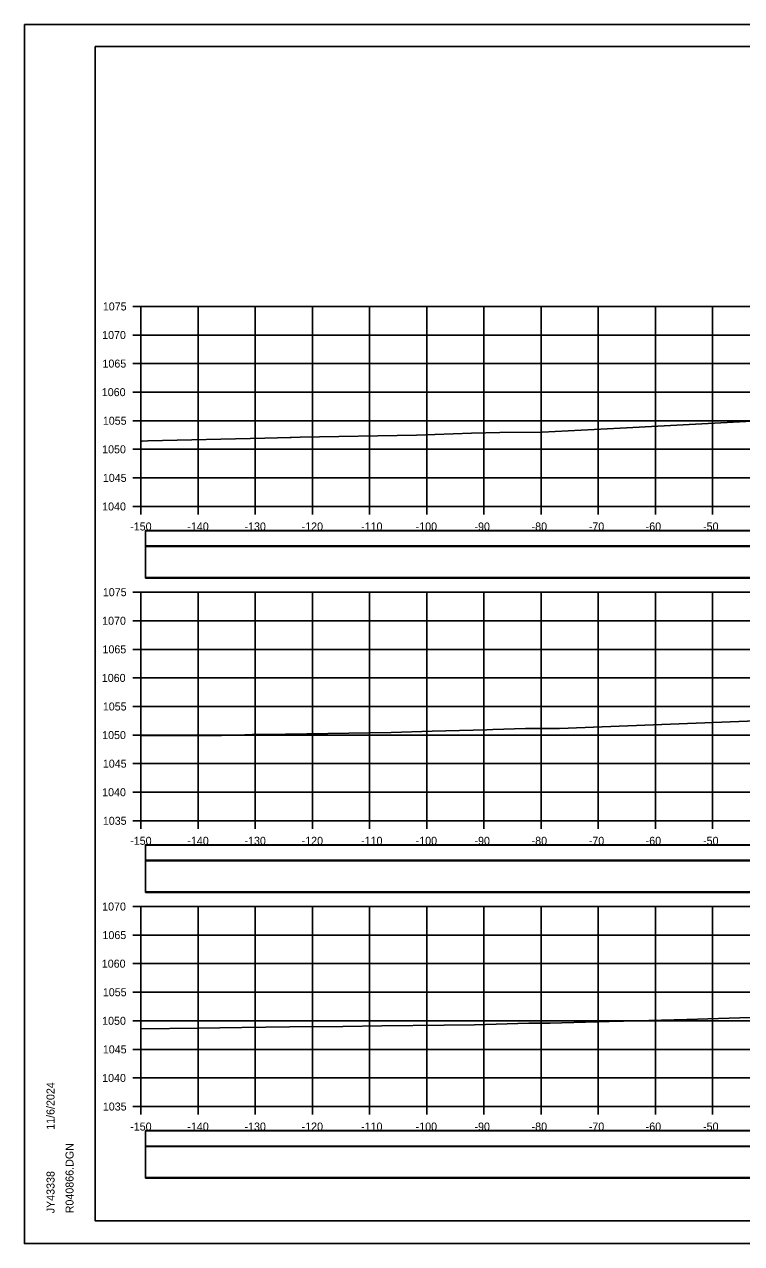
# Model space of a CAD drawing. Extents: x 1370565 to 1374448, y 301010 to 304637.
# Drawn here: x 1373198.4 to 1373323.9, y 303431.7 to 303645 of the extents above; entities that cross this region are included whole.
import ezdxf

# ---------------------------------------------------------------- set-up
doc = ezdxf.new("R2010")
doc.units = 0
for name, color, linetype in [('Default', 7, 'Continuous'), ('R_Axis', 7, 'Continuous'), ('R_Axis Annot', 7, 'Continuous'), ('R_Border', 7, 'Continuous'), ('R_Drive', 7, 'Continuous'), ('R_Exist Surface', 7, 'Continuous'), ('R_Grid', 7, 'Continuous'), ('R_No Plot', 7, 'Continuous')]:
    doc.layers.add(name, color=color, linetype=linetype)

msp = doc.modelspace()

# ---------------------------------------------------------------- linework, layer by layer
at = {"layer": 'Default'}
for points in [[(1373219.61, 303553.72), (1373518.02, 303553.72), (1373518.02, 303556.42), (1373219.61, 303556.42)], [(1373219.61, 303548.14), (1373518.02, 303548.14), (1373518.02, 303553.66), (1373219.61, 303553.66)], [(1373219.61, 303498.72), (1373518.02, 303498.72), (1373518.02, 303501.42), (1373219.61, 303501.42)], [(1373219.61, 303493.14), (1373518.02, 303493.14), (1373518.02, 303498.66), (1373219.61, 303498.66)], [(1373219.61, 303448.72), (1373518.02, 303448.72), (1373518.02, 303451.42), (1373219.61, 303451.42)], [(1373219.61, 303443.14), (1373518.02, 303443.14), (1373518.02, 303448.66), (1373219.61, 303448.66)]]:
    msp.add_lwpolyline(points, close=True, dxfattribs=at)
at = {"layer": 'R_Axis'}
for p, q in [((1373217.41, 303595.68), (1373218.81, 303595.68)), ((1373218.81, 303560.68), (1373218.81, 303595.68)), ((1373217.41, 303590.68), (1373218.81, 303590.68)), ((1373217.41, 303585.68), (1373218.81, 303585.68)), ((1373217.41, 303580.68), (1373218.81, 303580.68)), ((1373217.41, 303575.68), (1373218.81, 303575.68)), ((1373217.41, 303570.68), (1373218.81, 303570.68)), ((1373217.41, 303565.68), (1373218.81, 303565.68)), ((1373217.41, 303560.68), (1373218.81, 303560.68)), ((1373218.81, 303560.68), (1373518.81, 303560.68)), ((1373218.81, 303559.28), (1373218.81, 303560.68)), ((1373228.81, 303559.28), (1373228.81, 303560.68)), ((1373238.81, 303559.28), (1373238.81, 303560.68)), ((1373248.81, 303559.28), (1373248.81, 303560.68)), ((1373258.81, 303559.28), (1373258.81, 303560.68)), ((1373268.81, 303559.28), (1373268.81, 303560.68)), ((1373278.81, 303559.28), (1373278.81, 303560.68)), ((1373288.81, 303559.28), (1373288.81, 303560.68)), ((1373298.81, 303559.28), (1373298.81, 303560.68)), ((1373308.81, 303559.28), (1373308.81, 303560.68)), ((1373318.81, 303559.28), (1373318.81, 303560.68)), ((1373217.41, 303545.68), (1373218.81, 303545.68)), ((1373218.81, 303505.68), (1373218.81, 303545.68)), ((1373217.41, 303540.68), (1373218.81, 303540.68)), ((1373217.41, 303535.68), (1373218.81, 303535.68)), ((1373217.41, 303530.68), (1373218.81, 303530.68)), ((1373217.41, 303525.68), (1373218.81, 303525.68)), ((1373217.41, 303520.68), (1373218.81, 303520.68)), ((1373217.41, 303515.68), (1373218.81, 303515.68)), ((1373217.41, 303510.68), (1373218.81, 303510.68)), ((1373217.41, 303505.68), (1373218.81, 303505.68)), ((1373218.81, 303505.68), (1373518.81, 303505.68)), ((1373218.81, 303504.28), (1373218.81, 303505.68)), ((1373228.81, 303504.28), (1373228.81, 303505.68)), ((1373238.81, 303504.28), (1373238.81, 303505.68)), ((1373248.81, 303504.28), (1373248.81, 303505.68)), ((1373258.81, 303504.28), (1373258.81, 303505.68)), ((1373268.81, 303504.28), (1373268.81, 303505.68)), ((1373278.81, 303504.28), (1373278.81, 303505.68)), ((1373288.81, 303504.28), (1373288.81, 303505.68)), ((1373298.81, 303504.28), (1373298.81, 303505.68)), ((1373308.81, 303504.28), (1373308.81, 303505.68)), ((1373318.81, 303504.28), (1373318.81, 303505.68)), ((1373217.41, 303490.68), (1373218.81, 303490.68)), ((1373218.81, 303455.68), (1373218.81, 303490.68)), ((1373217.41, 303485.68), (1373218.81, 303485.68)), ((1373217.41, 303480.68), (1373218.81, 303480.68)), ((1373217.41, 303475.68), (1373218.81, 303475.68)), ((1373217.41, 303470.68), (1373218.81, 303470.68)), ((1373217.41, 303465.68), (1373218.81, 303465.68)), ((1373217.41, 303460.68), (1373218.81, 303460.68)), ((1373217.41, 303455.68), (1373218.81, 303455.68)), ((1373218.81, 303455.68), (1373518.81, 303455.68)), ((1373218.81, 303454.28), (1373218.81, 303455.68)), ((1373228.81, 303454.28), (1373228.81, 303455.68)), ((1373238.81, 303454.28), (1373238.81, 303455.68)), ((1373248.81, 303454.28), (1373248.81, 303455.68)), ((1373258.81, 303454.28), (1373258.81, 303455.68)), ((1373268.81, 303454.28), (1373268.81, 303455.68)), ((1373278.81, 303454.28), (1373278.81, 303455.68)), ((1373288.81, 303454.28), (1373288.81, 303455.68)), ((1373298.81, 303454.28), (1373298.81, 303455.68)), ((1373308.81, 303454.28), (1373308.81, 303455.68)), ((1373318.81, 303454.28), (1373318.81, 303455.68))]:
    msp.add_line(p, q, dxfattribs=at)
at = {"layer": 'R_Border'}
for p, q in [((1373210.81, 303641.14), (1373526.99, 303641.14)), ((1373210.81, 303435.68), (1373210.81, 303641.14)), ((1373210.81, 303435.68), (1373210.81, 303435.68)), ((1373526.99, 303435.68), (1373210.81, 303435.68))]:
    msp.add_line(p, q, dxfattribs=at)
at = {"layer": 'R_Drive'}
for points in [[(1373219.61, 303553.77), (1373518.02, 303553.77), (1373518.02, 303556.48), (1373219.61, 303556.48)], [(1373219.61, 303548.25), (1373518.02, 303548.25), (1373518.02, 303553.77), (1373219.61, 303553.77)], [(1373219.61, 303498.77), (1373518.02, 303498.77), (1373518.02, 303501.48), (1373219.61, 303501.48)], [(1373219.61, 303493.25), (1373518.02, 303493.25), (1373518.02, 303498.77), (1373219.61, 303498.77)], [(1373219.61, 303448.77), (1373518.02, 303448.77), (1373518.02, 303451.48), (1373219.61, 303451.48)], [(1373219.61, 303443.25), (1373518.02, 303443.25), (1373518.02, 303448.77), (1373219.61, 303448.77)]]:
    msp.add_lwpolyline(points, close=True, dxfattribs=at)
at = {"layer": 'R_Exist Surface'}
for points in [[(1373218.81, 303572.1), (1373219, 303572.11), (1373220, 303572.14), (1373240.48, 303572.64), (1373244.9, 303572.74), (1373245.06, 303572.75), (1373246.66, 303572.78), (1373267.01, 303573.13), (1373276.66, 303573.49), (1373281.59, 303573.65), (1373289.01, 303573.66), (1373302.64, 303574.38), (1373333.45, 303576.04)], [(1373218.81, 303520.52), (1373224.48, 303520.58), (1373230.1, 303520.6), (1373232.89, 303520.63), (1373236.96, 303520.72), (1373238.26, 303520.77), (1373240.42, 303520.79), (1373262.6, 303521.14), (1373269.76, 303521.39), (1373279.32, 303521.58), (1373280.38, 303521.67), (1373286.08, 303521.82), (1373292.02, 303521.81), (1373335.35, 303523.5)], [(1373218.81, 303469.29), (1373218.89, 303469.29), (1373228.77, 303469.41), (1373236.47, 303469.5), (1373244.83, 303469.6), (1373254.14, 303469.71), (1373260.97, 303469.79), (1373271.88, 303469.92), (1373277.17, 303469.98), (1373286.65, 303470.24), (1373290.39, 303470.28), (1373300.72, 303470.57), (1373303.23, 303470.6), (1373314.34, 303470.93), (1373327.26, 303471.31)]]:
    msp.add_lwpolyline(points, dxfattribs=at)
at = {"layer": 'R_Grid'}
for p, q in [((1373218.81, 303595.68), (1373518.81, 303595.68)), ((1373218.81, 303560.68), (1373218.81, 303595.68)), ((1373228.81, 303560.68), (1373228.81, 303595.68)), ((1373238.81, 303560.68), (1373238.81, 303595.68)), ((1373248.81, 303560.68), (1373248.81, 303595.68)), ((1373258.81, 303560.68), (1373258.81, 303595.68)), ((1373268.81, 303560.68), (1373268.81, 303595.68)), ((1373278.81, 303560.68), (1373278.81, 303595.68)), ((1373288.81, 303560.68), (1373288.81, 303595.68)), ((1373298.81, 303560.68), (1373298.81, 303595.68)), ((1373308.81, 303560.68), (1373308.81, 303595.68)), ((1373318.81, 303560.68), (1373318.81, 303595.68)), ((1373218.81, 303590.68), (1373518.81, 303590.68)), ((1373218.81, 303585.68), (1373518.81, 303585.68)), ((1373218.81, 303580.68), (1373518.81, 303580.68)), ((1373218.81, 303575.68), (1373518.81, 303575.68)), ((1373218.81, 303570.68), (1373518.81, 303570.68)), ((1373218.81, 303565.68), (1373518.81, 303565.68)), ((1373218.81, 303560.68), (1373518.81, 303560.68)), ((1373218.81, 303545.68), (1373518.81, 303545.68)), ((1373218.81, 303505.68), (1373218.81, 303545.68)), ((1373228.81, 303505.68), (1373228.81, 303545.68)), ((1373238.81, 303505.68), (1373238.81, 303545.68)), ((1373248.81, 303505.68), (1373248.81, 303545.68)), ((1373258.81, 303505.68), (1373258.81, 303545.68)), ((1373268.81, 303505.68), (1373268.81, 303545.68)), ((1373278.81, 303505.68), (1373278.81, 303545.68)), ((1373288.81, 303505.68), (1373288.81, 303545.68)), ((1373298.81, 303505.68), (1373298.81, 303545.68)), ((1373308.81, 303505.68), (1373308.81, 303545.68)), ((1373318.81, 303505.68), (1373318.81, 303545.68)), ((1373218.81, 303540.68), (1373518.81, 303540.68)), ((1373218.81, 303535.68), (1373518.81, 303535.68)), ((1373218.81, 303530.68), (1373518.81, 303530.68)), ((1373218.81, 303525.68), (1373518.81, 303525.68)), ((1373218.81, 303520.68), (1373518.81, 303520.68)), ((1373218.81, 303515.68), (1373518.81, 303515.68)), ((1373218.81, 303510.68), (1373518.81, 303510.68)), ((1373218.81, 303505.68), (1373518.81, 303505.68)), ((1373218.81, 303490.68), (1373518.81, 303490.68)), ((1373218.81, 303455.68), (1373218.81, 303490.68)), ((1373228.81, 303455.68), (1373228.81, 303490.68)), ((1373238.81, 303455.68), (1373238.81, 303490.68)), ((1373248.81, 303455.68), (1373248.81, 303490.68)), ((1373258.81, 303455.68), (1373258.81, 303490.68)), ((1373268.81, 303455.68), (1373268.81, 303490.68)), ((1373278.81, 303455.68), (1373278.81, 303490.68)), ((1373288.81, 303455.68), (1373288.81, 303490.68)), ((1373298.81, 303455.68), (1373298.81, 303490.68)), ((1373308.81, 303455.68), (1373308.81, 303490.68)), ((1373318.81, 303455.68), (1373318.81, 303490.68)), ((1373218.81, 303485.68), (1373518.81, 303485.68)), ((1373218.81, 303480.68), (1373518.81, 303480.68)), ((1373218.81, 303475.68), (1373518.81, 303475.68)), ((1373218.81, 303470.68), (1373518.81, 303470.68)), ((1373218.81, 303465.68), (1373518.81, 303465.68)), ((1373218.81, 303460.68), (1373518.81, 303460.68)), ((1373218.81, 303455.68), (1373518.81, 303455.68))]:
    msp.add_line(p, q, dxfattribs=at)
at = {"layer": 'R_No Plot'}
for p, q in [((1373198.41, 303645.03), (1373531.75, 303645.03)), ((1373198.41, 303431.7), (1373531.75, 303431.7))]:
    msp.add_line(p, q, dxfattribs=at)
for points in [[(1373198.41, 303645.03), (1373531.75, 303645.03), (1373531.75, 303431.7), (1373198.41, 303431.7)], [(1373444.73, 303641.14), (1373464.35, 303641.14), (1373464.35, 303631.26), (1373480.47, 303631.26), (1373503.67, 303631.26), (1373503.67, 303606.93), (1373526.99, 303606.93), (1373526.99, 303435.68), (1373210.81, 303435.68), (1373210.81, 303641.14)]]:
    msp.add_lwpolyline(points, close=True, dxfattribs=at)

# ---------------------------------------------------------------- texts
at = {"layer": 'R_Axis Annot'}
for s, p in [('1075', (1373212.13, 303594.98)), ('1070', (1373212.01, 303589.98)), ('1065', (1373212.07, 303584.98)), ('1060', (1373211.95, 303579.98)), ('1055', (1373212.13, 303574.98)), ('1050', (1373212.01, 303569.98)), ('1045', (1373212.13, 303564.98)), ('1040', (1373212.01, 303559.98)), ('-150', (1373216.92, 303556.48)), ('-140', (1373226.92, 303556.48)), ('-130', (1373236.92, 303556.48)), ('-120', (1373246.92, 303556.48)), ('-110', (1373257.32, 303556.48)), ('-100', (1373266.87, 303556.48)), ('-90', (1373277.16, 303556.48)), ('-80', (1373287.16, 303556.48)), ('-70', (1373297.16, 303556.48)), ('-60', (1373307.12, 303556.48)), ('-50', (1373317.16, 303556.48)), ('1075', (1373212.13, 303544.98)), ('1070', (1373212.01, 303539.98)), ('1065', (1373212.07, 303534.98)), ('1060', (1373211.95, 303529.98)), ('1055', (1373212.13, 303524.98)), ('1050', (1373212.01, 303519.98)), ('1045', (1373212.13, 303514.98)), ('1040', (1373212.01, 303509.98)), ('1035', (1373212.13, 303504.98)), ('-150', (1373216.92, 303501.48)), ('-140', (1373226.92, 303501.48)), ('-130', (1373236.92, 303501.48)), ('-120', (1373246.92, 303501.48)), ('-110', (1373257.32, 303501.48)), ('-100', (1373266.87, 303501.48)), ('-90', (1373277.16, 303501.48)), ('-80', (1373287.16, 303501.48)), ('-70', (1373297.16, 303501.48)), ('-60', (1373307.12, 303501.48)), ('-50', (1373317.16, 303501.48)), ('1070', (1373212.01, 303489.98)), ('1065', (1373212.07, 303484.98)), ('1060', (1373211.95, 303479.98)), ('1055', (1373212.13, 303474.98)), ('1050', (1373212.01, 303469.98)), ('1045', (1373212.13, 303464.98)), ('1040', (1373212.01, 303459.98)), ('1035', (1373212.13, 303454.98)), ('-150', (1373216.92, 303451.48)), ('-140', (1373226.92, 303451.48)), ('-130', (1373236.92, 303451.48)), ('-120', (1373246.92, 303451.48)), ('-110', (1373257.32, 303451.48)), ('-100', (1373266.87, 303451.48)), ('-90', (1373277.16, 303451.48)), ('-80', (1373287.16, 303451.48)), ('-70', (1373297.16, 303451.48)), ('-60', (1373307.12, 303451.48)), ('-50', (1373317.16, 303451.48))]:
    msp.add_text(s, height=1.4, dxfattribs=at).set_placement(p)
at = {"layer": 'R_Border'}
for s, p in [('11/6/2024', (1373203.68, 303451.61)), ('R040866.DGN', (1373207.01, 303437)), ('JY43338', (1373203.68, 303437))]:
    msp.add_text(s, height=1.4, rotation=90, dxfattribs=at).set_placement(p)

doc.saveas('drawing.dxf')
